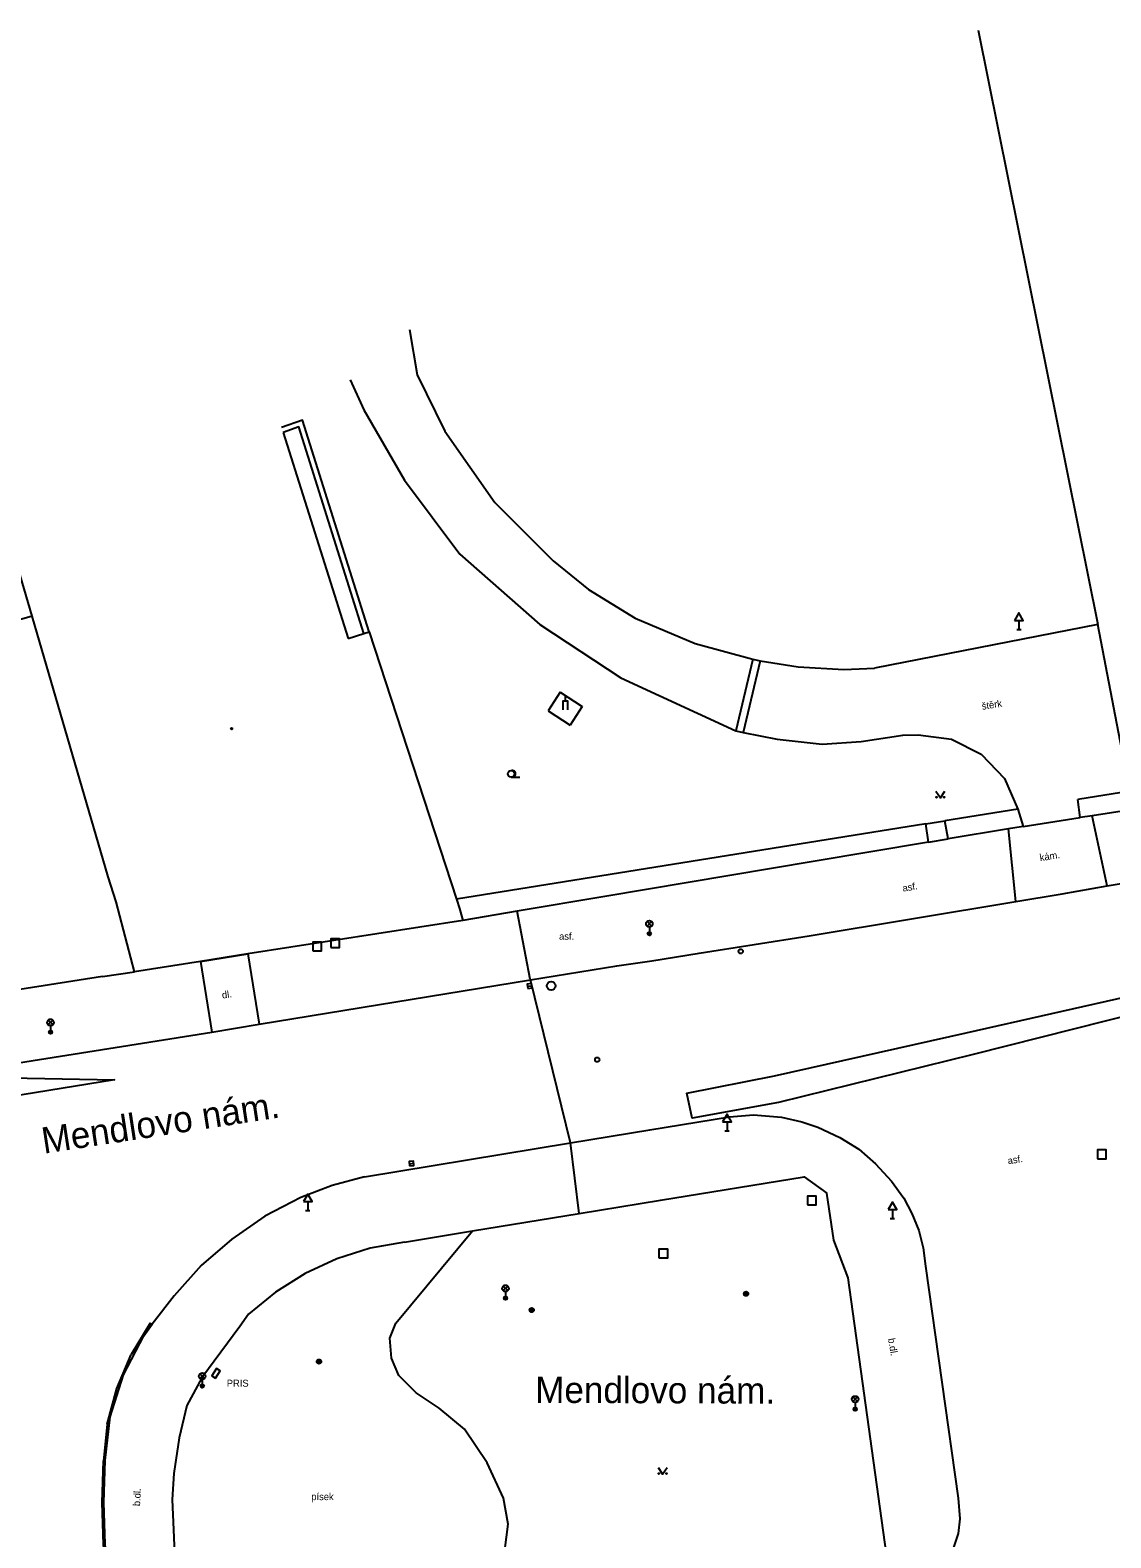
# Model space of a CAD drawing. Extents: x -599770 to -598493, y -1162076 to -1159209.
# Drawn here: x -599305.9 to -599244.1, y -1161159.4 to -1161073.2 of the extents above; entities that cross this region are included whole.
import ezdxf

# ---------------------------------------------------------------- set-up
doc = ezdxf.new("R2010")
doc.units = 0
doc.layers.add('Podklad', color=7, linetype='Continuous')

msp = doc.modelspace()

# ---------------------------------------------------------------- linework, layer by layer
at = {"layer": 'Podklad'}
for p, q in [((-599249.505, -1161107.44), (-599249.255, -1161107.44)), ((-599249.38, -1161106.931), (-599249.38, -1161107.44)), ((-599275.3, -1161111.53), (-599275.3, -1161111.265)), ((-599278.4, -1161115.878), (-599277.9, -1161115.878)), ((-599270.633, -1161124.4), (-599270.368, -1161124.135)), ((-599270.633, -1161124.135), (-599270.368, -1161124.4)), ((-599270.5, -1161124.455), (-599270.5, -1161124.83)), ((-599277.464, -1161127.834), (-599277.216, -1161127.806)), ((-599304.852, -1161130.03), (-599304.587, -1161129.765)), ((-599304.852, -1161129.765), (-599304.587, -1161130.03)), ((-599304.72, -1161130.085), (-599304.72, -1161130.46)), ((-599266.06, -1161135.581), (-599266.06, -1161136.09)), ((-599266.185, -1161136.09), (-599265.935, -1161136.09)), ((-599284.214, -1161137.974), (-599283.966, -1161137.946)), ((-599290.02, -1161140.141), (-599290.02, -1161140.65)), ((-599290.145, -1161140.65), (-599289.895, -1161140.65)), ((-599256.61, -1161140.601), (-599256.61, -1161141.11)), ((-599256.735, -1161141.11), (-599256.485, -1161141.11)), ((-599278.852, -1161145.23), (-599278.587, -1161144.965)), ((-599278.852, -1161144.965), (-599278.587, -1161145.23)), ((-599278.72, -1161145.285), (-599278.72, -1161145.66)), ((-599296.183, -1161150.25), (-599295.918, -1161149.985)), ((-599296.183, -1161149.985), (-599295.918, -1161150.25)), ((-599296.05, -1161150.305), (-599296.05, -1161150.68)), ((-599258.872, -1161151.57), (-599258.607, -1161151.305)), ((-599258.872, -1161151.305), (-599258.607, -1161151.57)), ((-599258.74, -1161151.625), (-599258.74, -1161152))]:
    msp.add_line(p, q, dxfattribs=at)
for points in [[(-599251.7, -1161073.2), (-599244.86, -1161107.16)], [(-599284.2, -1161090.31), (-599283.76, -1161092.89), (-599282.19, -1161096.12), (-599279.34, -1161100.19), (-599275.99, -1161103.53), (-599273.97, -1161105.16), (-599271.31, -1161106.81), (-599267.88, -1161108.24), (-599264.58, -1161109.14)], [(-599287.6, -1161093.18), (-599286.82, -1161094.89), (-599284.5, -1161098.92), (-599281.33, -1161103.14), (-599276.76, -1161107.17), (-599272.13, -1161110.21), (-599265.55, -1161113.23)], [(-599286.52, -1161107.58), (-599290.33, -1161095.49), (-599291.52, -1161095.9)], [(-599286.81, -1161107.67), (-599290.54, -1161095.86), (-599291.42, -1161096.2)], [(-599291.42, -1161096.2), (-599287.72, -1161107.97)], [(-599305.77, -1161106.69), (-599307.5, -1161100.77)], [(-599305.77, -1161106.69), (-599334.12, -1161114.8)], [(-599301.42, -1161121.58), (-599305.77, -1161106.69)], [(-599244.86, -1161107.16), (-599257.63, -1161109.65)], [(-599243.04, -1161116.68), (-599244.86, -1161107.16)], [(-599287.72, -1161107.97), (-599286.81, -1161107.67)], [(-599286.81, -1161107.67), (-599286.52, -1161107.58)], [(-599286.52, -1161107.58), (-599281.53, -1161122.85)], [(-599264.58, -1161109.14), (-599265.55, -1161113.23)], [(-599264.58, -1161109.14), (-599264.17, -1161109.23)], [(-599264.17, -1161109.23), (-599265.14, -1161113.33)], [(-599264.17, -1161109.23), (-599262, -1161109.59), (-599259.38, -1161109.73), (-599257.63, -1161109.65)], [(-599275.6, -1161111.03), (-599276.29, -1161112.09)], [(-599275.6, -1161111.03), (-599274.34, -1161111.85)], [(-599275.425, -1161112.03), (-599275.425, -1161111.53), (-599275.175, -1161111.53), (-599275.175, -1161112.03)], [(-599276.29, -1161112.09), (-599275.03, -1161112.91)], [(-599274.34, -1161111.85), (-599275.03, -1161112.91)], [(-599265.55, -1161113.23), (-599265.14, -1161113.33)], [(-599265.14, -1161113.33), (-599263.19, -1161113.71), (-599260.62, -1161114.01), (-599258.4, -1161113.84), (-599256.02, -1161113.48), (-599255.13, -1161113.46), (-599253.24, -1161113.71), (-599251.53, -1161114.57), (-599250.21, -1161115.96), (-599249.44, -1161117.71)], [(-599254.12, -1161116.685), (-599253.87, -1161117.06), (-599253.62, -1161116.685)], [(-599241.77, -1161116.48), (-599243.04, -1161116.68), (-599246.01, -1161117.16)], [(-599249.44, -1161117.71), (-599253.61, -1161118.38)], [(-599249.44, -1161117.71), (-599249.13, -1161118.7)], [(-599245.88, -1161118.19), (-599246.01, -1161117.16)], [(-599241.63, -1161117.55), (-599245.2, -1161118.09)], [(-599254.7, -1161118.55), (-599281.53, -1161122.85)], [(-599254.7, -1161118.55), (-599253.61, -1161118.38)], [(-599254.54, -1161119.61), (-599254.7, -1161118.55)], [(-599253.42, -1161119.42), (-599253.61, -1161118.38)], [(-599249.13, -1161118.7), (-599245.88, -1161118.19)], [(-599245.2, -1161118.09), (-599245.88, -1161118.19)], [(-599244.34, -1161122.1), (-599245.2, -1161118.09)], [(-599254.54, -1161119.61), (-599253.42, -1161119.42)], [(-599249.98, -1161118.84), (-599253.42, -1161119.42)], [(-599249.25, -1161118.72), (-599249.98, -1161118.84)], [(-599249.55, -1161122.99), (-599249.98, -1161118.84)], [(-599249.13, -1161118.7), (-599249.25, -1161118.72)], [(-599254.54, -1161119.61), (-599261.13, -1161120.7), (-599273.04, -1161122.7), (-599278.06, -1161123.55), (-599281.16, -1161124.07)], [(-599300.97, -1161123.01), (-599301.42, -1161121.58)], [(-599249.55, -1161122.99), (-599246.9, -1161122.55), (-599244.34, -1161122.1)], [(-599244.34, -1161122.1), (-599243.42, -1161121.94)], [(-599292.8, -1161130.01), (-599277.296, -1161127.469), (-599272.36, -1161126.66), (-599270.36, -1161126.38), (-599267.65, -1161125.94), (-599261.36, -1161124.96), (-599249.55, -1161122.99)], [(-599281.53, -1161122.85), (-599281.35, -1161123.4)], [(-599299.93, -1161127.01), (-599300.97, -1161123.01)], [(-599281.35, -1161123.4), (-599281.16, -1161124.07)], [(-599274.52, -1161140.82), (-599275.014, -1161136.786), (-599275.015, -1161136.774), (-599277.296, -1161127.469), (-599277.307, -1161127.424), (-599278.06, -1161123.55)], [(-599281.16, -1161124.07), (-599293.45, -1161125.99)], [(-599301.75, -1161127.28), (-599320.3, -1161130.2), (-599326.18, -1161131.12), (-599336.3, -1161127.44), (-599337.41, -1161126.2)], [(-599296.15, -1161126.42), (-599299.93, -1161127.01)], [(-599296.15, -1161126.42), (-599293.45, -1161125.99)], [(-599293.45, -1161125.99), (-599296.15, -1161126.42)], [(-599296.15, -1161126.42), (-599295.51, -1161130.45)], [(-599293.45, -1161125.99), (-599292.8, -1161130.01)], [(-599301.75, -1161127.28), (-599299.93, -1161127.01)], [(-599242.61, -1161128.29), (-599242.41, -1161129.31), (-599251.99, -1161131.74), (-599263.11, -1161134.48), (-599268.05, -1161135.38), (-599268.36, -1161133.94), (-599263.35, -1161132.96), (-599252.39, -1161130.5), (-599242.61, -1161128.29)], [(-599310.05, -1161133.02), (-599301.07, -1161133.19), (-599320.66, -1161136.37), (-599321.035, -1161136.422), (-599322.03, -1161136.56), (-599324.41, -1161136.61), (-599327.04, -1161136.38), (-599329.8, -1161135.77), (-599332.23, -1161134.94), (-599333.343, -1161134.538), (-599335.53, -1161133.75), (-599338.97, -1161132.08), (-599341.44, -1161130.54)], [(-599318.82, -1161134.16), (-599295.51, -1161130.45)], [(-599295.51, -1161130.45), (-599292.8, -1161130.01)], [(-599286.77, -1161138.72), (-599275.014, -1161136.786), (-599270.48, -1161136.04), (-599265.91, -1161135.3)], [(-599265.91, -1161135.3), (-599264.55, -1161135.18), (-599262.95, -1161135.31), (-599261.79, -1161135.58), (-599260.87, -1161135.89), (-599259.62, -1161136.47), (-599258.53, -1161137.15), (-599257.57, -1161137.99), (-599256.66, -1161138.98), (-599255.95, -1161139.94), (-599255.49, -1161140.83), (-599255.1, -1161141.79), (-599254.85, -1161142.79)], [(-599286.77, -1161138.72), (-599288.62, -1161139.23), (-599290.42, -1161139.9), (-599292.47, -1161140.97), (-599294.37, -1161142.28), (-599296.11, -1161143.8), (-599297.65, -1161145.52), (-599298.92, -1161147.14)], [(-599280.61, -1161141.82), (-599274.52, -1161140.82), (-599269.86, -1161140.06), (-599261.66, -1161138.73), (-599260.36, -1161139.66)], [(-599256.95, -1161160.29), (-599259.13, -1161144.5), (-599259.95, -1161142.35), (-599260.36, -1161139.66)], [(-599296.53, -1161167.95), (-599292.36, -1161165.16), (-599291.48, -1161164.94), (-599290.32, -1161165.2), (-599287.68, -1161166.38), (-599286.8, -1161166.63), (-599285.1, -1161166.26), (-599283.58, -1161165.82), (-599281.47, -1161164.55), (-599279.71, -1161163.14), (-599278.87, -1161160.96), (-599278.57, -1161158.58), (-599278.84, -1161157.08), (-599279.76, -1161155.06), (-599281.07, -1161153.15), (-599282.51, -1161151.95), (-599283.83, -1161151.06), (-599284.82, -1161150.08), (-599285.24, -1161149.09), (-599285.33, -1161147.95), (-599284.98, -1161147.08), (-599280.61, -1161141.82)], [(-599284.49, -1161142.45), (-599280.61, -1161141.82)], [(-599284.49, -1161142.45), (-599286.45, -1161142.81), (-599288.36, -1161143.41), (-599290.17, -1161144.25), (-599291.86, -1161145.31), (-599293.4, -1161146.57), (-599293.9, -1161147.27), (-599296.08, -1161150.21), (-599296.93, -1161151.8)], [(-599254.85, -1161142.79), (-599254.71, -1161143.83), (-599252.86, -1161157.09), (-599252.75, -1161158.27)], [(-599299.02, -1161147.09), (-599300.12, -1161148.88)], [(-599299.02, -1161147.09), (-599298.92, -1161147.14)], [(-599301.6, -1161154.94), (-599301.31, -1161152.44), (-599300.56, -1161150.04), (-599299.39, -1161147.82)], [(-599299.39, -1161147.82), (-599298.92, -1161147.14)], [(-599301.48, -1161152.86), (-599300.94, -1161150.82), (-599300.12, -1161148.88)], [(-599296.93, -1161151.8), (-599297.373, -1161153.643), (-599297.68, -1161155.67), (-599297.778, -1161157.17), (-599297.7, -1161158.9), (-599297.616, -1161160.696), (-599297.251, -1161163.412), (-599296.53, -1161167.95)], [(-599301.48, -1161152.86), (-599301.7, -1161154.95)], [(-599301.15, -1161164.48), (-599301.49, -1161162.11), (-599301.7, -1161159.73), (-599301.77, -1161157.34), (-599301.7, -1161154.95)], [(-599301.02, -1161164.47), (-599301.38, -1161162.11), (-599301.6, -1161159.72), (-599301.67, -1161157.33), (-599301.6, -1161154.94)], [(-599269.99, -1161155.335), (-599269.74, -1161155.71), (-599269.49, -1161155.335)], [(-599252.75, -1161158.27), (-599252.86, -1161159.1), (-599253.171, -1161160.073), (-599253.78, -1161161.26), (-599254.834, -1161162.648), (-599256.2, -1161164.16)]]:
    msp.add_lwpolyline(points, dxfattribs=at)
for points in [[(-599249.63, -1161106.931), (-599249.13, -1161106.931), (-599249.38, -1161106.498)], [(-599289.73, -1161125.82), (-599289.23, -1161125.82), (-599289.23, -1161125.32), (-599289.73, -1161125.32)], [(-599288.7, -1161125.63), (-599288.2, -1161125.63), (-599288.2, -1161125.13), (-599288.7, -1161125.13)], [(-599277.45, -1161127.958), (-599277.202, -1161127.93), (-599277.23, -1161127.682), (-599277.478, -1161127.71)], [(-599266.31, -1161135.581), (-599265.81, -1161135.581), (-599266.06, -1161135.148)], [(-599244.89, -1161137.69), (-599244.39, -1161137.69), (-599244.39, -1161137.19), (-599244.89, -1161137.19)], [(-599284.2, -1161138.098), (-599283.952, -1161138.07), (-599283.98, -1161137.822), (-599284.228, -1161137.85)], [(-599290.27, -1161140.141), (-599289.77, -1161140.141), (-599290.02, -1161139.708)], [(-599261.47, -1161140.33), (-599260.97, -1161140.33), (-599260.97, -1161139.83), (-599261.47, -1161139.83)], [(-599256.86, -1161140.601), (-599256.36, -1161140.601), (-599256.61, -1161140.168)], [(-599269.95, -1161143.36), (-599269.45, -1161143.36), (-599269.45, -1161142.86), (-599269.95, -1161142.86)], [(-599295.299, -1161150.238), (-599295.03, -1161149.817), (-599295.241, -1161149.682), (-599295.51, -1161150.103)]]:
    msp.add_lwpolyline(points, close=True, dxfattribs=at)
for centre, radius in [((-599294.37, -1161113.12), 0.045), ((-599294.37, -1161113.12), 0.0199), ((-599278.4, -1161115.69), 0.188), ((-599254.095, -1161117.035), 0.025), ((-599253.645, -1161117.035), 0.025), ((-599270.5, -1161124.267), 0.188), ((-599270.5, -1161124.83), 0.1), ((-599270.5, -1161124.83), 0.0723), ((-599270.5, -1161124.83), 0.0438), ((-599265.28, -1161125.84), 0.125), ((-599276.11, -1161127.81), 0.25), ((-599304.72, -1161129.898), 0.188), ((-599304.72, -1161130.46), 0.1), ((-599304.72, -1161130.46), 0.0723), ((-599304.72, -1161130.46), 0.0438), ((-599273.48, -1161132.03), 0.125), ((-599278.72, -1161145.097), 0.188), ((-599264.97, -1161145.41), 0.125), ((-599264.97, -1161145.41), 0.1), ((-599264.97, -1161145.41), 0.075), ((-599264.97, -1161145.41), 0.05), ((-599264.97, -1161145.41), 0.025), ((-599278.72, -1161145.66), 0.1), ((-599278.72, -1161145.66), 0.0723), ((-599278.72, -1161145.66), 0.0438), ((-599277.22, -1161146.34), 0.125), ((-599277.22, -1161146.34), 0.1), ((-599277.22, -1161146.34), 0.075), ((-599277.22, -1161146.34), 0.05), ((-599277.22, -1161146.34), 0.025), ((-599289.38, -1161149.28), 0.125), ((-599289.38, -1161149.28), 0.1), ((-599289.38, -1161149.28), 0.075), ((-599289.38, -1161149.28), 0.05), ((-599289.38, -1161149.28), 0.025), ((-599296.05, -1161150.117), 0.188), ((-599296.05, -1161150.68), 0.1), ((-599296.05, -1161150.68), 0.0723), ((-599296.05, -1161150.68), 0.0438), ((-599258.74, -1161151.438), 0.188), ((-599258.74, -1161152), 0.1), ((-599258.74, -1161152), 0.0723), ((-599258.74, -1161152), 0.0438), ((-599269.965, -1161155.685), 0.025), ((-599269.515, -1161155.685), 0.025)]:
    msp.add_circle(centre, radius, dxfattribs=at)
msp.add_arc((-599278.337, -1161115.69), 0.188, 260.40593, 99.59407, dxfattribs=at)

# ---------------------------------------------------------------- texts
for s, height, rotation, p in [('štěrk', 0.4, 9, (-599251.47, -1161112.04)), ('kám.', 0.4, 9, (-599248.16, -1161120.69)), ('asf.', 0.4, 9, (-599256, -1161122.43)), ('dl.', 0.4, 7.88, (-599294.9, -1161128.54)), ('Mendlovo nám.', 1.5, 8.75, (-599305.11, -1161137.41)), ('asf.', 0.4, 9, (-599249.99, -1161138.01)), ('b.dl.', 0.4, 279.72, (-599256.86, -1161147.98)), ('Mendlovo nám.', 1.5, 359.79, (-599277.03, -1161151.64)), ('b.dl.', 0.4, 86.87, (-599299.61, -1161157.55))]:
    msp.add_text(s, height=height, rotation=rotation, dxfattribs=at).set_placement(p)
for s, p in [('asf.', (-599275.66, -1161125.18)), ('PRIS', (-599294.65, -1161150.72)), ('písek', (-599289.82, -1161157.2))]:
    msp.add_text(s, height=0.4, dxfattribs=at).set_placement(p)

doc.saveas('drawing.dxf')
